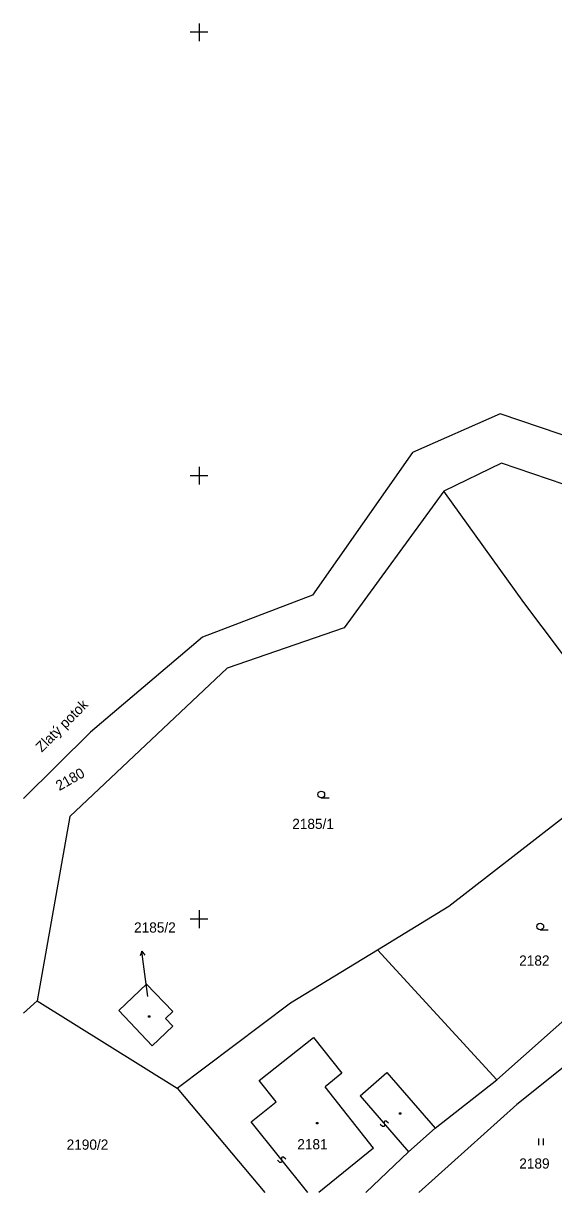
# Model space of a CAD drawing. Extents: x -504375 to -503125, y -1118000 to -1116474.
# Drawn here: x -503819.8 to -503760, y -1117230.8 to -1117099 of the extents above; entities that cross this region are included whole.
import ezdxf

# ---------------------------------------------------------------- set-up
doc = ezdxf.new("R2010")
doc.units = 0
doc.layers.add('Podkladové mapy', color=7, linetype='Continuous')
doc.layers.add('Vrstva 34', color=7, linetype='Continuous')

msp = doc.modelspace()

# ---------------------------------------------------------------- linework, layer by layer
at = {"layer": 'Podkladové mapy'}
for p, q in [((-503766.06, -1117143.02), (-503775.91, -1117147.39)), ((-503754.76, -1117146.84), (-503766.06, -1117143.02)), ((-503775.91, -1117147.39), (-503787.21, -1117163.45)), ((-503765.88, -1117148.58), (-503772.41, -1117151.76)), ((-503754.67, -1117152.43), (-503765.88, -1117148.58)), ((-503772.41, -1117151.76), (-503783.62, -1117167.16)), ((-503763.38, -1117164.31), (-503772.41, -1117151.76)), ((-503787.21, -1117163.45), (-503799.61, -1117168.19)), ((-503750.22, -1117181.77), (-503763.38, -1117164.31)), ((-503783.62, -1117167.16), (-503796.84, -1117171.68)), ((-503799.61, -1117168.19), (-503812.23, -1117178.92)), ((-503796.84, -1117171.68), (-503814.58, -1117188.43)), ((-503812.23, -1117178.92), (-503819.807, -1117186.39)), ((-503771.84, -1117198.53), (-503750.22, -1117181.77)), ((-503786.21, -1117186.32), (-503785.335, -1117186.32)), ((-503814.58, -1117188.43), (-503818.26, -1117209.19)), ((-503766.42, -1117218.1), (-503740.13, -1117194.75)), ((-503779.89, -1117203.45), (-503771.84, -1117198.53)), ((-503761.52, -1117201.19), (-503760.645, -1117201.19)), ((-503806.443, -1117203.592), (-503806.627, -1117204.12)), ((-503806.25, -1117205.08), (-503806.443, -1117203.592)), ((-503806.443, -1117203.592), (-503806.13, -1117204.056)), ((-503789.7, -1117209.44), (-503779.89, -1117203.45)), ((-503779.89, -1117203.45), (-503766.42, -1117218.1)), ((-503805.78, -1117208.72), (-503806.25, -1117205.08)), ((-503744.95, -1117205.51), (-503764.18, -1117220.91)), ((-503809.05, -1117210.28), (-503805.91, -1117207.31)), ((-503802.94, -1117210.42), (-503805.91, -1117207.31)), ((-503818.26, -1117209.19), (-503819.807, -1117210.612)), ((-503818.26, -1117209.19), (-503802.46, -1117219.04)), ((-503802.46, -1117219.04), (-503789.7, -1117209.44)), ((-503805.28, -1117214.27), (-503809.05, -1117210.28)), ((-503805.7, -1117210.89), (-503805.55, -1117210.89)), ((-503805.7, -1117211.04), (-503805.7, -1117210.89)), ((-503805.55, -1117211.04), (-503805.7, -1117211.04)), ((-503805.55, -1117210.89), (-503805.55, -1117211.04)), ((-503803.77, -1117211.21), (-503802.94, -1117210.42)), ((-503803.77, -1117211.21), (-503802.96, -1117212.08)), ((-503802.96, -1117212.08), (-503805.28, -1117214.27)), ((-503793.22, -1117218.18), (-503787.11, -1117213.34)), ((-503787.11, -1117213.34), (-503783.89, -1117217.35)), ((-503783.89, -1117217.35), (-503785.79, -1117218.9)), ((-503781.84, -1117219.9), (-503778.82, -1117217.27)), ((-503778.82, -1117217.27), (-503773.36, -1117223.58)), ((-503802.46, -1117219.04), (-503792.59, -1117230.829)), ((-503791.31, -1117220.6), (-503793.22, -1117218.18)), ((-503780.34, -1117225.83), (-503785.79, -1117218.9)), ((-503773.36, -1117223.58), (-503766.42, -1117218.1)), ((-503781.84, -1117219.9), (-503776.38, -1117226.24)), ((-503794.13, -1117222.83), (-503791.31, -1117220.6)), ((-503764.18, -1117220.91), (-503775.218, -1117230.829)), ((-503787.731, -1117230.829), (-503794.13, -1117222.83)), ((-503786.74, -1117222.92), (-503786.59, -1117222.92)), ((-503786.74, -1117223.07), (-503786.74, -1117222.92)), ((-503786.59, -1117223.07), (-503786.74, -1117223.07)), ((-503786.59, -1117222.92), (-503786.59, -1117223.07)), ((-503779.127, -1117222.82), (-503779.137, -1117222.961)), ((-503779.137, -1117222.961), (-503779.082, -1117223.178)), ((-503779.051, -1117222.755), (-503779.127, -1117222.82)), ((-503778.91, -1117222.765), (-503779.051, -1117222.755)), ((-503778.643, -1117222.998), (-503778.91, -1117222.765)), ((-503777.41, -1117221.85), (-503777.26, -1117221.85)), ((-503777.41, -1117222), (-503777.41, -1117221.85)), ((-503777.26, -1117222), (-503777.41, -1117222)), ((-503777.26, -1117221.85), (-503777.26, -1117222)), ((-503779.31, -1117223.374), (-503779.576, -1117223.142)), ((-503779.169, -1117223.385), (-503779.31, -1117223.374)), ((-503779.093, -1117223.319), (-503779.169, -1117223.385)), ((-503779.082, -1117223.178), (-503779.093, -1117223.319)), ((-503776.38, -1117226.24), (-503773.36, -1117223.58)), ((-503761.69, -1117225.495), (-503761.69, -1117224.745)), ((-503761.19, -1117224.745), (-503761.19, -1117225.495)), ((-503790.698, -1117226.88), (-503790.713, -1117227.02)), ((-503790.713, -1117227.02), (-503790.666, -1117227.239)), ((-503790.619, -1117226.817), (-503790.698, -1117226.88)), ((-503790.479, -1117226.833), (-503790.619, -1117226.817)), ((-503790.221, -1117227.075), (-503790.479, -1117226.833)), ((-503780.34, -1117225.83), (-503786.508, -1117230.829)), ((-503781.202, -1117230.829), (-503776.38, -1117226.24)), ((-503790.901, -1117227.427), (-503791.159, -1117227.185)), ((-503790.76, -1117227.442), (-503790.901, -1117227.427)), ((-503790.682, -1117227.38), (-503790.76, -1117227.442)), ((-503790.666, -1117227.239), (-503790.682, -1117227.38))]:
    msp.add_line(p, q, dxfattribs=at)
for centre in [(-503786.21, -1117185.945), (-503761.52, -1117200.815)]:
    msp.add_circle(centre, 0.375, dxfattribs=at)
at = {"layer": 'Vrstva 34'}
for p, q in [((-503800, -1117099), (-503800, -1117101)), ((-503799, -1117100), (-503801, -1117100)), ((-503800, -1117149), (-503800, -1117151)), ((-503799, -1117150), (-503801, -1117150)), ((-503800, -1117199), (-503800, -1117201)), ((-503799, -1117200), (-503801, -1117200))]:
    msp.add_line(p, q, dxfattribs=at)

# ---------------------------------------------------------------- texts
at = {"layer": 'Podkladové mapy'}
for s, rotation, p in [('Zlatý potok', 45.01728, (-503817.727, -1117181.24)), ('2180', 29.4354, (-503815.75, -1117185.559))]:
    msp.add_text(s, height=1.15, rotation=rotation, dxfattribs=at).set_placement(p)
for s, p in [('2185/1', (-503789.49, -1117189.83)), ('2185/2', (-503807.328, -1117201.51)), ('2182', (-503763.9, -1117205.24)), ('2190/2', (-503814.93, -1117225.992)), ('2181', (-503788.92, -1117225.95)), ('2189', (-503763.889, -1117228.12))]:
    msp.add_text(s, height=1.15, dxfattribs=at).set_placement(p)

doc.saveas('drawing.dxf')
